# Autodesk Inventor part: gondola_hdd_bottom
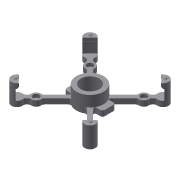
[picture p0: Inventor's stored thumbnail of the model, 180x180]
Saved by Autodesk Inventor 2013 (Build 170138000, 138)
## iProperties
Created: 2013-11
Part Number: gondola_hdd_bottom
Material: Generic
Document SubType Name: Modeling
Designer: Jonas
Density: 1 g/cm^3
Author: Jonas
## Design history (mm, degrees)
derived "gondola_hdd.ipt"
feature "Solid5::gondola_hdd.ipt" dims "d0" = 10
tag "TaggingFeature1"
body "Solid1"
